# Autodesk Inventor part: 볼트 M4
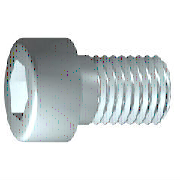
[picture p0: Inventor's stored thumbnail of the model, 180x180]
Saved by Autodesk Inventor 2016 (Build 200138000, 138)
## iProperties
IsCustomPart: 1
Created: 2012-02
Part Number: 볼트 M4
Material: 강철, 연강
Description: 6각머리 태핑 나사
Document SubType Name: Modeling
Standard: KS B 1003
Designer: mduedu
Standards Organization: KS
Language: ko-KR
Size Designation: M 4 x 10
Categories: <MemberInstance><Categories><Category DisplayName="조임쇠" InternalName="e4da775c-781d-43d5-af7c-5136215cf5a6" Mnemonic="FSTN"><Category DisplayName="볼트" InternalN
Density: 1 g/cm^3
Appearance: 강철
Author: mduedu
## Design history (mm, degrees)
sketch "스케치1"
  geometry: L1 (-1, 0)-(10, 0); L2 (10, 0)-(10, 2); L3 (10, 2)-(1.75, 2); L4 (1.75, 2)-(1.32, 2); L5 (1.32, 2)-(0, 2); L6 (0, 2)-(0, 3.5); L7 (0, 3.5)-(-4, 3.5); L8 (-4, 3.5)-(-4, 1.732); L9 (-4, 1.732)-(-2, 1.732); L10 (-2, 1.732)-(-1, 0); L11 (-6.8, 0)-(12.8, 0) reference; L12 (0, -0.7)-(0, 4.2) reference; L13 (1.75, 2)-(0, 2)
  constraints: 22 end point, 6 parallel, 2 collinear, 2 perpendicular, 1 horizontal, 1 point on line
  dimensions: "d1" = 8.25 distance from line of L3.end L2 (= GEL); "d2" = 0.42952 distance of L4.end L3.end (computed from GAL); "d3" = 4 distance between parallel lines of L8 L6 (= KOH); "d4" = 2 distance of L8.end L9.end (= INTI); "d5" = 60 deg angle of L10 L1; "d6" = 4 diameter of L3 L1 (= GD); "d7" = 4 diameter of L5 L1 (= BDM); "d8" = 3.4641 diameter of L9 L1 (= 1.1547 x SW); "d9" = 7 diameter of L7 L1 (= KOD); "d26" = 10 distance between parallel lines of L12 L2 (= NLG)
revolve "본체" sketch "스케치1" stored, may be unused: angle "d10" = 90 deg
sketch "스케치2"
  geometry: L1 (0, -4.9)-(0, 4.9) reference; L2 (-4.9, 0)-(4.9, 0) reference; L3 (1.732, 0)-(0.866, -1.5); L4 (0.866, -1.5)-(-0.866, -1.5); L5 (-0.866, -1.5)-(-1.732, 0); L6 (-1.732, 0)-(-0.866, 1.5); L7 (-0.866, 1.5)-(0.866, 1.5); L8 (0.866, 1.5)-(1.732, 0); 2 further points
  constraints: 12 end point, 1 coincident, 1 horizontal alignment, 1 point on line, 12 other
extrude "슬롯" join sketch "스케치2" stored distance "d11" = 10; taper "d12" = 0 deg
workplane "Work Plane1"
fillet "Fillet2" dims "d30" = 0.1 (= R)
body "Solid1"
fillet "모깎기1" dims "d17" = 0.4 (= RR)
feature "스레드" dims "d13" = 8.25 (= GEL), "d14" = 0
chamfer "모따기1" distance "d15" = 0.42941 (= -0.5 x SPD + 0.5 x GD); stored, may be unused: second distance "d16" = 0.42941 (= GUL), angle "d27" = 45 deg
other parameters: "GD" = 4 (= NND) [user parameter; used in 2 equation terms], "NLG" = 10 [user parameter; used in 1 equation term], "GEL" = 8.25 [user parameter; used in 2 equation terms], "KOD" = 7 [user parameter; used in 1 equation term], "KOH" = 4 [user parameter; used in 1 equation term], "INTI" = 2 [user parameter; used in 1 equation term], "GAL" = 0.42941 (= 0.61345 x PTC) [user parameter; used in 1 equation term], "GUL" = 0.42941 (= 0.61345 x PTC) [user parameter; used in 1 equation term], "BDM" = 4 (= NND) [user parameter; used in 1 equation term], "SW" = 3 [user parameter; used in 2 equation terms], "RR" = 0.4 [user parameter; used in 1 equation term], "SPD" = 3.14117 (= NND - 1.2269 x PTC) [user parameter; used in 1 equation term], "d19" = 0, "d28" = 0, "d29" = 0, "R" = 0.1 [user parameter; used in 1 equation term], "PHH" = 0.2 [user parameter], "GD1" = 3.14117 (= THREADDIA - 1.2269 x PTC) [user parameter], "THREADDIA" = 4 [user parameter; used in 1 equation term], "FAWI" = 45 deg [user parameter], "TPU" = 14.28571 (computed from PTC) [user parameter], "PTC" = 0.7 [user parameter; used in 5 equation terms], "NND" = 4 [user parameter; used in 3 equation terms], "TOA" = 30 deg [user parameter], "E0" = 3.465 (= 1.155 x SW) [user parameter]
